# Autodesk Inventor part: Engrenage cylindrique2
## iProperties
Created: 2011-10
Part Number: Engrenage cylindrique2
Material: Steel
Document SubType Name: Modeling
Designer: Laur
Density: 1 g/cm^3
CustomPartVersion: 1
Author: Laur
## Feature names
1. Extrusion1
2. Extrusion2
